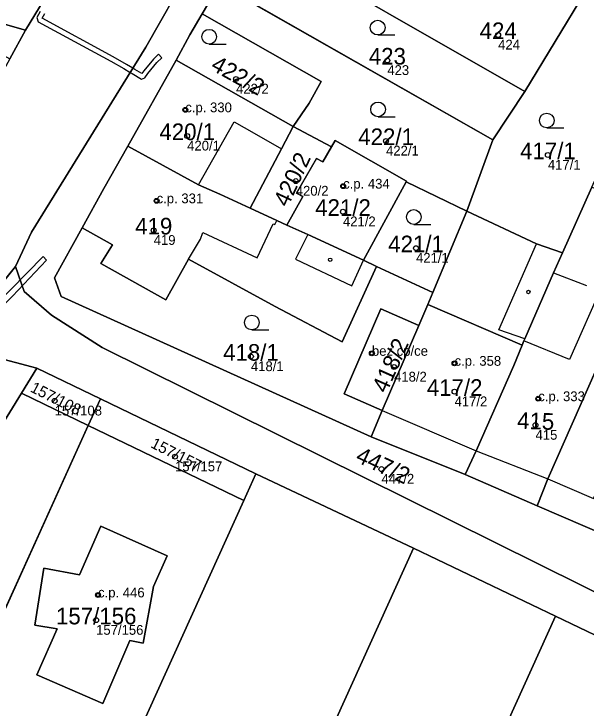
# Model space of a CAD drawing. Extents: x -603967 to -594699, y -1179315 to -1165625.
# Drawn here: x -598148.1 to -598089.7, y -1172456.2 to -1172385.2 of the extents above; entities that cross this region are included whole.
import ezdxf

# ---------------------------------------------------------------- set-up
doc = ezdxf.new("R2010")
doc.units = 0
for name, color, linetype in [('Definiční body', 7, 'Continuous'), ('Hranice parcel', 7, 'Continuous'), ('Parcelní čísla', 7, 'Continuous'), ('Polygon budovy', 7, 'Continuous'), ('Polygon parcely', 7, 'Continuous'), ('Vnitřní kresba', 7, 'Continuous'), ('Věcná břemena k části', 7, 'Continuous'), ('Značky budov', 7, 'Continuous'), ('Značky kultur', 7, 'Continuous')]:
    doc.layers.add(name, color=color, linetype=linetype)

msp = doc.modelspace()

# ---------------------------------------------------------------- linework, layer by layer
at = {"layer": 'Definiční body'}
for centre in [(-598098.67, -1172387.36994), (-598109.99, -1172389.96994), (-598125.44, -1172391.86994), (-598130.62, -1172395.01994), (-598130.43, -1172397.68994), (-598110.12, -1172398.19994), (-598093.59, -1172399.63994), (-598119.34, -1172402.29994), (-598114.5, -1172402.81994), (-598133.55, -1172404.31994), (-598114.52, -1172405.42994), (-598133.85, -1172407.32994), (-598107.06, -1172409.14994), (-598111.56, -1172419.89994), (-598123.92, -1172420.22994), (-598109.3, -1172421.29994), (-598103.12, -1172420.91994), (-598103.12, -1172423.81994), (-598143.96, -1172424.75994), (-598094.57, -1172424.53994), (-598094.85, -1172427.23994), (-598131.67, -1172430.45994), (-598110.59, -1172431.72994), (-598139.53, -1172444.58994), (-598139.73, -1172447.16994)]:
    msp.add_circle(centre, 0.25, dxfattribs=at)
at = {"layer": 'Hranice parcel'}
for p, q in [((-598124.18, -1172376.97), (-598095.93, -1172393.13)), ((-598127.12, -1172382.17), (-598128.91, -1172385.22)), ((-598099.22, -1172398.09), (-598127.12, -1172382.17)), ((-598146.94, -1172386.87), (-598160.87, -1172382.88)), ((-598089.74, -1172382.91), (-598095.93, -1172393.13)), ((-598145.05, -1172383.72), (-598146.94, -1172386.87)), ((-598128.91, -1172385.22), (-598116.73, -1172392.11)), ((-598148.54, -1172389.81), (-598146.94, -1172386.87)), ((-598136.48, -1172398.72), (-598131.55, -1172389.93)), ((-598119.62, -1172396.71), (-598131.55, -1172389.93)), ((-598116.73, -1172392.11), (-598117.98, -1172394.35)), ((-598095.93, -1172393.13), (-598099.22, -1172398.09)), ((-598117.98, -1172394.35), (-598119.62, -1172396.71)), ((-598115.7, -1172398.81), (-598119.62, -1172396.71)), ((-598115.7, -1172398.81), (-598115.31, -1172398.14)), ((-598115.31, -1172398.14), (-598108.02, -1172402.3)), ((-598099.22, -1172398.09), (-598101.87, -1172405.38)), ((-598116.58, -1172400.34), (-598115.7, -1172398.81)), ((-598108.05, -1172402.36), (-598112.41, -1172410.39)), ((-598108.02, -1172402.3), (-598108.05, -1172402.36)), ((-598108.05, -1172402.36), (-598101.87, -1172405.38)), ((-598089.1, -1172402.93), (-598092.11, -1172409.63)), ((-598105.34, -1172413.68), (-598101.87, -1172405.38)), ((-598138.07, -1172408.8), (-598141.15, -1172407.08)), ((-598111.09, -1172411.02), (-598112.41, -1172410.39)), ((-598151.96, -1172415.97), (-598147.97, -1172411.03)), ((-598111.09, -1172411.02), (-598105.34, -1172413.68)), ((-598114.41, -1172424.04), (-598110.65, -1172415.34)), ((-598110.65, -1172415.34), (-598106.77, -1172417.07)), ((-598110.5, -1172425.74), (-598106.77, -1172417.07)), ((-598145.78, -1172421.43), (-598150.17, -1172420.25)), ((-598147.35, -1172423.96), (-598145.78, -1172421.43)), ((-598145.78, -1172421.43), (-598139.29, -1172424.54)), ((-598197.25, -1172505.23), (-598147.35, -1172423.96)), ((-598140.53, -1172427.28), (-598147.35, -1172423.96)), ((-598110.5, -1172425.74), (-598114.41, -1172424.04)), ((-598140.53, -1172427.28), (-598139.29, -1172424.54)), ((-598139.29, -1172424.54), (-598123.41, -1172432.22)), ((-598111.65, -1172428.42), (-598110.5, -1172425.74)), ((-598140.53, -1172427.28), (-598179.48, -1172513.27)), ((-598124.65, -1172434.95), (-598140.53, -1172427.28)), ((-598102.04, -1172432.27), (-598111.65, -1172428.42)), ((-598123.41, -1172432.22), (-598124.65, -1172434.95)), ((-598107.31, -1172439.82), (-598123.41, -1172432.22)), ((-598102.04, -1172432.27), (-598094.68, -1172435.47)), ((-598124.65, -1172434.95), (-598165.48, -1172525.1)), ((-598087.34, -1172438.66), (-598094.68, -1172435.47)), ((-598191.44, -1172625.54), (-598107.31, -1172439.82)), ((-598092.8, -1172446.77), (-598107.31, -1172439.82)), ((-598092.8, -1172446.77), (-598078.3, -1172453.72))]:
    msp.add_line(p, q, dxfattribs=at)
for points in [[(-598075.77, -1172286.95), (-598091.8, -1172313.57), (-598105.37, -1172338.1), (-598121.26, -1172365.09), (-598134.65, -1172388.61), (-598146.32, -1172407.52), (-598147.97, -1172411.03)], [(-598131.55, -1172389.93), (-598130.16, -1172387.36), (-598128.91, -1172385.22)], [(-598119.62, -1172396.71), (-598120.8, -1172398.99), (-598123.98, -1172405.08)], [(-598136.48, -1172398.72), (-598138.93, -1172403.05), (-598141.15, -1172407.08)], [(-598123.98, -1172405.08), (-598127.09, -1172403.65), (-598129.28, -1172402.67), (-598136.48, -1172398.72)], [(-598120.25, -1172406.79), (-598118.61, -1172403.89), (-598119.25, -1172403.53), (-598117.22, -1172399.98), (-598116.58, -1172400.34)], [(-598123.98, -1172405.08), (-598121.28, -1172406.32), (-598120.25, -1172406.79)], [(-598101.87, -1172405.38), (-598094.75, -1172408.72), (-598092.11, -1172409.63)], [(-598141.15, -1172407.08), (-598143.99, -1172412.19), (-598143.31, -1172414.11), (-598111.65, -1172428.42)], [(-598112.41, -1172410.39), (-598118.1, -1172407.75), (-598120.25, -1172406.79)], [(-598132.61, -1172414.42), (-598139.26, -1172410.72), (-598138.07, -1172408.8)], [(-598092.11, -1172409.63), (-598093, -1172411.67), (-598095.95, -1172418.42), (-598096.03, -1172418.61), (-598096.23, -1172419.06), (-598097.05, -1172421.15), (-598100.9, -1172429.87), (-598102.04, -1172432.27)], [(-598111.09, -1172411.02), (-598114.6, -1172418.71), (-598121.43, -1172415.12), (-598130.28, -1172410.29), (-598132.61, -1172414.42)], [(-598147.97, -1172411.03), (-598147.07, -1172413.58), (-598144.3, -1172416.01), (-598139.1, -1172419.32), (-598081.13, -1172448.09)], [(-598106.77, -1172417.07), (-598105.85, -1172414.92), (-598105.34, -1172413.68)], [(-598094.68, -1172435.47), (-598093.59, -1172432.71), (-598085.35, -1172414.11), (-598085.21, -1172413.8)], [(-598139.26, -1172437.57), (-598132.47, -1172440.58), (-598133.88, -1172443.72), (-598134.92, -1172449.5), (-598136.28, -1172449.26), (-598139.05, -1172455.68), (-598145.77, -1172452.76), (-598143.7, -1172448.05), (-598146, -1172447.66), (-598145.08, -1172441.86), (-598141.42, -1172442.52), (-598139.26, -1172437.57)], [(-598176.73, -1172632.2), (-598134.77, -1172539.49), (-598092.8, -1172446.77)]]:
    msp.add_lwpolyline(points, dxfattribs=at)
at = {"layer": 'Polygon budovy'}
for points in [[(-598131.55, -1172389.93), (-598136.48, -1172398.72), (-598129.28, -1172402.67), (-598125.63, -1172396.25), (-598123.57, -1172397.39), (-598120.8, -1172398.99), (-598119.62, -1172396.71)], [(-598118.61, -1172403.89), (-598120.25, -1172406.79), (-598118.1, -1172407.75), (-598112.41, -1172410.39), (-598108.05, -1172402.36), (-598108.02, -1172402.3), (-598115.31, -1172398.14), (-598115.7, -1172398.81), (-598116.58, -1172400.34), (-598117.22, -1172399.98), (-598119.25, -1172403.53)], [(-598138.93, -1172403.05), (-598141.15, -1172407.08), (-598138.07, -1172408.8), (-598139.26, -1172410.72), (-598132.61, -1172414.42), (-598130.28, -1172410.29), (-598129.07, -1172408.25), (-598128.83, -1172407.54), (-598123.28, -1172410.15), (-598121.64, -1172406.68), (-598121.49, -1172406.74), (-598121.28, -1172406.32), (-598123.98, -1172405.08), (-598127.09, -1172403.65), (-598129.28, -1172402.67), (-598136.48, -1172398.72)], [(-598096.23, -1172419.06), (-598097.05, -1172421.15), (-598100.9, -1172429.87), (-598093.59, -1172432.71), (-598085.35, -1172414.11), (-598088.02, -1172412.9), (-598091.39, -1172420.52), (-598096.03, -1172418.61)], [(-598085.35, -1172414.11), (-598093.59, -1172432.71), (-598088.93, -1172434.75), (-598084.28, -1172424.46), (-598086.86, -1172423.58), (-598083.13, -1172414.69), (-598085.21, -1172413.8)], [(-598097.05, -1172421.15), (-598096.23, -1172419.06), (-598105.85, -1172414.92), (-598106.77, -1172417.07), (-598110.5, -1172425.74), (-598100.9, -1172429.87)], [(-598110.65, -1172415.34), (-598114.41, -1172424.04), (-598110.5, -1172425.74), (-598106.77, -1172417.07)], [(-598139.26, -1172437.57), (-598141.42, -1172442.52), (-598145.08, -1172441.86), (-598146, -1172447.66), (-598143.7, -1172448.05), (-598145.77, -1172452.76), (-598139.05, -1172455.68), (-598136.28, -1172449.26), (-598134.92, -1172449.5), (-598133.88, -1172443.72), (-598132.47, -1172440.58)]]:
    msp.add_lwpolyline(points, close=True, dxfattribs=at)
at = {"layer": 'Polygon parcely'}
for points in [[(-598143.52, -1172381.06), (-598144.09, -1172383.53), (-598144.75, -1172383.2), (-598145.05, -1172383.72), (-598146.94, -1172386.87), (-598148.54, -1172389.81), (-598158.56, -1172408.18), (-598161.65, -1172411.31), (-598151.96, -1172415.97), (-598147.97, -1172411.03), (-598146.32, -1172407.52), (-598134.65, -1172388.61), (-598121.26, -1172365.09), (-598105.37, -1172338.1), (-598091.8, -1172313.57), (-598075.77, -1172286.95), (-598088.59, -1172284.27), (-598101.24, -1172308.1), (-598115.07, -1172331.82), (-598127, -1172352.44), (-598142.53, -1172379.36)], [(-598174.32, -1172374.49), (-598160.87, -1172382.88), (-598146.94, -1172386.87), (-598145.05, -1172383.72), (-598146.71, -1172382.73), (-598151.63, -1172379.8), (-598151.99, -1172379.59), (-598144.08, -1172348.4), (-598140.78, -1172335.38), (-598146.67, -1172325.94), (-598148.36, -1172325.06), (-598158.21, -1172343.24)], [(-598108.39, -1172379.2), (-598109.33, -1172380.73), (-598116.11, -1172376.88), (-598115.24, -1172375.34), (-598121.22, -1172371.71), (-598124.18, -1172376.97), (-598095.93, -1172393.13), (-598089.74, -1172382.91), (-598093.08, -1172380.99), (-598098.74, -1172377.74), (-598099.81, -1172379.7), (-598101.62, -1172383.02)], [(-598099.22, -1172398.09), (-598095.93, -1172393.13), (-598124.18, -1172376.97), (-598127.12, -1172382.17)], [(-598108.05, -1172402.36), (-598101.87, -1172405.38), (-598099.22, -1172398.09), (-598127.12, -1172382.17), (-598128.91, -1172385.22), (-598116.73, -1172392.11), (-598117.98, -1172394.35), (-598119.62, -1172396.71), (-598115.7, -1172398.81), (-598115.31, -1172398.14), (-598108.02, -1172402.3)], [(-598146.94, -1172386.87), (-598160.87, -1172382.88), (-598148.54, -1172389.81)], [(-598089.1, -1172402.93), (-598082.21, -1172387.57), (-598089.74, -1172382.91), (-598095.93, -1172393.13), (-598099.22, -1172398.09), (-598101.87, -1172405.38), (-598094.75, -1172408.72), (-598092.11, -1172409.63)], [(-598116.73, -1172392.11), (-598128.91, -1172385.22), (-598130.16, -1172387.36), (-598131.55, -1172389.93), (-598119.62, -1172396.71), (-598117.98, -1172394.35)], [(-598131.55, -1172389.93), (-598136.48, -1172398.72), (-598129.28, -1172402.67), (-598127.09, -1172403.65), (-598123.98, -1172405.08), (-598120.8, -1172398.99), (-598119.62, -1172396.71)], [(-598120.25, -1172406.79), (-598118.61, -1172403.89), (-598119.25, -1172403.53), (-598117.22, -1172399.98), (-598116.58, -1172400.34), (-598115.7, -1172398.81), (-598119.62, -1172396.71), (-598120.8, -1172398.99), (-598123.98, -1172405.08), (-598121.28, -1172406.32)], [(-598116.58, -1172400.34), (-598117.22, -1172399.98), (-598119.25, -1172403.53), (-598118.61, -1172403.89), (-598120.25, -1172406.79), (-598118.1, -1172407.75), (-598112.41, -1172410.39), (-598108.05, -1172402.36), (-598108.02, -1172402.3), (-598115.31, -1172398.14), (-598115.7, -1172398.81)], [(-598112.41, -1172410.39), (-598118.1, -1172407.75), (-598120.25, -1172406.79), (-598121.28, -1172406.32), (-598123.98, -1172405.08), (-598127.09, -1172403.65), (-598129.28, -1172402.67), (-598136.48, -1172398.72), (-598138.93, -1172403.05), (-598141.15, -1172407.08), (-598138.07, -1172408.8), (-598139.26, -1172410.72), (-598132.61, -1172414.42), (-598130.28, -1172410.29), (-598121.43, -1172415.12), (-598114.6, -1172418.71), (-598111.09, -1172411.02)], [(-598105.34, -1172413.68), (-598101.87, -1172405.38), (-598108.05, -1172402.36), (-598112.41, -1172410.39), (-598111.09, -1172411.02)], [(-598093.59, -1172432.71), (-598085.35, -1172414.11), (-598085.21, -1172413.8), (-598083.03, -1172408.99), (-598087.77, -1172407.11), (-598086.53, -1172404.12), (-598089.1, -1172402.93), (-598092.11, -1172409.63), (-598093, -1172411.67), (-598095.95, -1172418.42), (-598096.03, -1172418.61), (-598096.23, -1172419.06), (-598097.05, -1172421.15), (-598100.9, -1172429.87), (-598102.04, -1172432.27), (-598094.68, -1172435.47)], [(-598105.34, -1172413.68), (-598105.85, -1172414.92), (-598106.77, -1172417.07), (-598110.5, -1172425.74), (-598111.65, -1172428.42), (-598102.04, -1172432.27), (-598100.9, -1172429.87), (-598097.05, -1172421.15), (-598096.23, -1172419.06), (-598096.03, -1172418.61), (-598095.95, -1172418.42), (-598093, -1172411.67), (-598092.11, -1172409.63), (-598094.75, -1172408.72), (-598101.87, -1172405.38)], [(-598130.28, -1172410.29), (-598132.61, -1172414.42), (-598139.26, -1172410.72), (-598138.07, -1172408.8), (-598141.15, -1172407.08), (-598143.99, -1172412.19), (-598143.31, -1172414.11), (-598111.65, -1172428.42), (-598110.5, -1172425.74), (-598114.41, -1172424.04), (-598110.65, -1172415.34), (-598106.77, -1172417.07), (-598105.85, -1172414.92), (-598105.34, -1172413.68), (-598111.09, -1172411.02), (-598114.6, -1172418.71), (-598121.43, -1172415.12)], [(-598077.8, -1172416.84), (-598083.13, -1172414.69), (-598085.21, -1172413.8), (-598085.35, -1172414.11), (-598093.59, -1172432.71), (-598094.68, -1172435.47), (-598087.34, -1172438.66), (-598086.03, -1172435.86), (-598078.73, -1172419.34)], [(-598110.5, -1172425.74), (-598106.77, -1172417.07), (-598110.65, -1172415.34), (-598114.41, -1172424.04)], [(-598226.32, -1172546.22), (-598226.22, -1172553.01), (-598221.79, -1172545.44), (-598197.25, -1172505.23), (-598147.35, -1172423.96), (-598145.78, -1172421.43), (-598150.17, -1172420.25), (-598154.69, -1172419.34), (-598161.24, -1172422.87), (-598236.93, -1172506.23), (-598240.72, -1172512.95), (-598242.5, -1172518.68), (-598243.32, -1172534.93), (-598243.18, -1172582.01), (-598234.02, -1172566.34), (-598234.08, -1172562.34), (-598234.2, -1172554.34), (-598234.32, -1172546.34)], [(-598139.29, -1172424.54), (-598145.78, -1172421.43), (-598147.35, -1172423.96), (-598140.53, -1172427.28)], [(-598140.53, -1172427.28), (-598147.35, -1172423.96), (-598197.25, -1172505.23), (-598179.48, -1172513.27)], [(-598124.65, -1172434.95), (-598123.41, -1172432.22), (-598139.29, -1172424.54), (-598140.53, -1172427.28)], [(-598124.65, -1172434.95), (-598140.53, -1172427.28), (-598179.48, -1172513.27), (-598181.54, -1172517.82), (-598165.48, -1172525.1)], [(-598165.48, -1172525.1), (-598207.65, -1172618.18), (-598191.44, -1172625.54), (-598107.31, -1172439.82), (-598123.41, -1172432.22), (-598124.65, -1172434.95)], [(-598139.26, -1172437.57), (-598132.47, -1172440.58), (-598133.88, -1172443.72), (-598134.92, -1172449.5), (-598136.28, -1172449.26), (-598139.05, -1172455.68), (-598145.77, -1172452.76), (-598143.7, -1172448.05), (-598146, -1172447.66), (-598145.08, -1172441.86), (-598141.42, -1172442.52)], [(-598139.26, -1172437.57), (-598141.42, -1172442.52), (-598145.08, -1172441.86), (-598146, -1172447.66), (-598143.7, -1172448.05), (-598145.77, -1172452.76), (-598139.05, -1172455.68), (-598136.28, -1172449.26), (-598134.92, -1172449.5), (-598133.88, -1172443.72), (-598132.47, -1172440.58)], [(-598176.73, -1172632.2), (-598134.77, -1172539.49), (-598092.8, -1172446.77), (-598107.31, -1172439.82), (-598191.44, -1172625.54)], [(-598078.3, -1172453.72), (-598092.8, -1172446.77), (-598134.77, -1172539.49), (-598176.73, -1172632.2), (-598162.02, -1172638.87), (-598120.17, -1172546.31)]]:
    msp.add_lwpolyline(points, close=True, dxfattribs=at)
for points in [[(-598121.26, -1172365.09), (-598134.65, -1172388.61), (-598146.32, -1172407.52), (-598147.97, -1172411.03), (-598147.07, -1172413.58), (-598144.3, -1172416.01), (-598139.1, -1172419.32), (-598081.13, -1172448.09), (-598079.05, -1172442.16), (-598087.34, -1172438.66), (-598094.68, -1172435.47), (-598102.04, -1172432.27), (-598111.65, -1172428.42), (-598143.31, -1172414.11), (-598143.99, -1172412.19), (-598141.15, -1172407.08), (-598138.93, -1172403.05), (-598136.48, -1172398.72), (-598131.55, -1172389.93), (-598130.16, -1172387.36), (-598128.91, -1172385.22), (-598127.12, -1172382.17)], [(-598058.38, -1172458.37), (-598068.66, -1172453.58), (-598081.13, -1172448.09), (-598139.1, -1172419.32), (-598144.3, -1172416.01), (-598147.07, -1172413.58), (-598147.97, -1172411.03), (-598151.96, -1172415.97), (-598154.69, -1172419.34), (-598150.17, -1172420.25), (-598145.78, -1172421.43), (-598139.29, -1172424.54), (-598123.41, -1172432.22), (-598107.31, -1172439.82), (-598092.8, -1172446.77), (-598078.3, -1172453.72), (-598073.12, -1172456.2), (-598063.82, -1172460.72), (-598054.46, -1172465.27)]]:
    msp.add_lwpolyline(points, dxfattribs=at)
at = {"layer": 'Vnitřní kresba'}
for p, q in [((-598129.28, -1172402.67), (-598125.63, -1172396.25)), ((-598125.63, -1172396.25), (-598123.57, -1172397.39)), ((-598123.57, -1172397.39), (-598120.8, -1172398.99)), ((-598121.49, -1172406.74), (-598121.28, -1172406.32)), ((-598123.28, -1172410.15), (-598121.64, -1172406.68)), ((-598121.64, -1172406.68), (-598121.49, -1172406.74)), ((-598129.07, -1172408.25), (-598128.83, -1172407.54)), ((-598128.83, -1172407.54), (-598123.28, -1172410.15)), ((-598118.1, -1172407.75), (-598119.35, -1172410.29)), ((-598130.28, -1172410.29), (-598129.07, -1172408.25)), ((-598098.61, -1172417.49), (-598094.75, -1172408.72)), ((-598119.35, -1172410.29), (-598113.61, -1172413.01)), ((-598113.61, -1172413.01), (-598112.41, -1172410.39)), ((-598093, -1172411.67), (-598089.63, -1172412.97)), ((-598088.02, -1172412.9), (-598091.39, -1172420.52)), ((-598105.85, -1172414.92), (-598096.23, -1172419.06)), ((-598095.95, -1172418.42), (-598098.61, -1172417.49)), ((-598091.39, -1172420.52), (-598096.03, -1172418.61)), ((-598110.5, -1172425.74), (-598100.9, -1172429.87)), ((-598100.9, -1172429.87), (-598093.59, -1172432.71)), ((-598093.59, -1172432.71), (-598088.93, -1172434.75))]:
    msp.add_line(p, q, dxfattribs=at)
at = {"layer": 'Věcná břemena k části'}
msp.add_lwpolyline([(-598145.44, -1172384.98), (-598145.77, -1172385.57), (-598145.66, -1172386.03), (-598138.22, -1172390.03), (-598136.9, -1172390.79), (-598136.24, -1172391.19), (-598136.05, -1172391.31), (-598135.1, -1172391.87), (-598134.76, -1172391.74), (-598134.45, -1172391.32), (-598133.51, -1172390.17), (-598133.01, -1172389.7), (-598133.35, -1172389.34), (-598133.87, -1172389.83), (-598134.85, -1172391.02), (-598135.06, -1172391.31), (-598135.79, -1172390.89), (-598135.98, -1172390.77), (-598136.64, -1172390.37), (-598137.98, -1172389.59), (-598145.23, -1172385.65), (-598144.98, -1172385.18)], dxfattribs=at)
msp.add_lwpolyline([(-598145.15, -1172410.02), (-598148.43, -1172413.38), (-598154.94, -1172420.06), (-598169.45, -1172434.97), (-598176.36, -1172439.52), (-598199.58, -1172454.84), (-598222.53, -1172479), (-598241.07, -1172498.39), (-598240.34, -1172512.28), (-598240.02, -1172518.39), (-598238.8, -1172519.43), (-598238.48, -1172519.05), (-598239.54, -1172518.15), (-598239.88, -1172511.47), (-598240.55, -1172498.57), (-598222.17, -1172479.34), (-598199.26, -1172455.22), (-598177.72, -1172441.02), (-598169.13, -1172435.35), (-598154.27, -1172420.09), (-598148.27, -1172414.06), (-598144.8, -1172410.37)], close=True, dxfattribs=at)
at = {"layer": 'Značky budov'}
for centre in [(-598130.6268, -1172395.01916), (-598114.5068, -1172402.81916), (-598133.5568, -1172404.31916), (-598115.8268, -1172410.33916), (-598095.5768, -1172413.62916), (-598111.5668, -1172419.89916), (-598103.1268, -1172420.91916), (-598094.5768, -1172424.53916), (-598139.5368, -1172444.58916)]:
    msp.add_circle(centre, 0.175, dxfattribs=at)
at = {"layer": 'Značky kultur'}
for p, q in [((-598110.973, -1172387.37), (-598109.223, -1172387.37)), ((-598128.183, -1172388.3), (-598126.433, -1172388.3)), ((-598110.933, -1172395.72), (-598109.183, -1172395.72)), ((-598093.703, -1172396.86), (-598091.953, -1172396.86)), ((-598107.283, -1172406.72), (-598105.533, -1172406.72)), ((-598123.823, -1172417.5), (-598122.073, -1172417.5))]:
    msp.add_line(p, q, dxfattribs=at)
for centre in [(-598110.97286, -1172386.61981), (-598128.18286, -1172387.54981), (-598110.93286, -1172394.96981), (-598093.70286, -1172396.10981), (-598107.28286, -1172405.96981), (-598123.82286, -1172416.74981)]:
    msp.add_circle(centre, 0.75, dxfattribs=at)

# ---------------------------------------------------------------- texts
at = {"layer": 'Definiční body'}
for s, p in [('424', (-598098.67, -1172388.859)), ('423', (-598109.99, -1172391.459)), ('422/2', (-598125.44, -1172393.359)), ('c.p. 330', (-598130.62, -1172395.27)), ('420/1', (-598130.43, -1172399.179)), ('422/1', (-598110.12, -1172399.689)), ('417/1', (-598093.59, -1172401.129)), ('c.p. 434', (-598114.5, -1172403.07)), ('420/2', (-598119.34, -1172403.789)), ('c.p. 331', (-598133.55, -1172404.57)), ('421/2', (-598114.52, -1172406.919)), ('419', (-598133.85, -1172408.819)), ('421/1', (-598107.06, -1172410.639)), ('bez cp/ce', (-598111.56, -1172420.15)), ('c.p. 358', (-598103.12, -1172421.17)), ('418/1', (-598123.92, -1172421.719)), ('418/2', (-598109.3, -1172422.789)), ('c.p. 333', (-598094.57, -1172424.79)), ('417/2', (-598103.12, -1172425.309)), ('157/108', (-598143.96, -1172426.249)), ('415', (-598094.85, -1172428.729)), ('157/157', (-598131.67, -1172431.949)), ('447/2', (-598110.59, -1172433.219)), ('c.p. 446', (-598139.53, -1172444.84)), ('157/156', (-598139.73, -1172448.659))]:
    msp.add_text(s, height=0.999996, dxfattribs=at).set_placement(p)
at = {"layer": 'Parcelní čísla'}
for s, p in [('424', (-598100.56, -1172387.795)), ('423', (-598111.88, -1172390.395)), ('420/1', (-598133.266, -1172398.115)), ('422/1', (-598112.956, -1172398.625)), ('417/1', (-598096.426, -1172400.065)), ('421/2', (-598117.356, -1172405.855)), ('419', (-598135.74, -1172407.755)), ('421/1', (-598109.896, -1172409.575)), ('418/1', (-598126.756, -1172420.655)), ('417/2', (-598105.956, -1172424.245)), ('157/156', (-598143.826, -1172447.595))]:
    msp.add_text(s, height=1.699998, dxfattribs=at).set_placement(p)
for s, height, rotation, p in [('422/2', 1.699998, 331, (-598128.126, -1172390.866)), ('420/2', 1.699998, 65, (-598120.153, -1172405.049)), ('418/2', 1.699998, 66, (-598110.065, -1172424.063)), ('157/108', 1.14, 333, (-598146.537, -1172423.766)), ('415', 1.699998, 358, (-598096.754, -1172427.598)), ('157/157', 1.138998, 333, (-598134.244, -1172429.467)), ('447/2', 1.699998, 335, (-598113.339, -1172430.916))]:
    msp.add_text(s, height=height, rotation=rotation, dxfattribs=at).set_placement(p)

doc.saveas('drawing.dxf')
